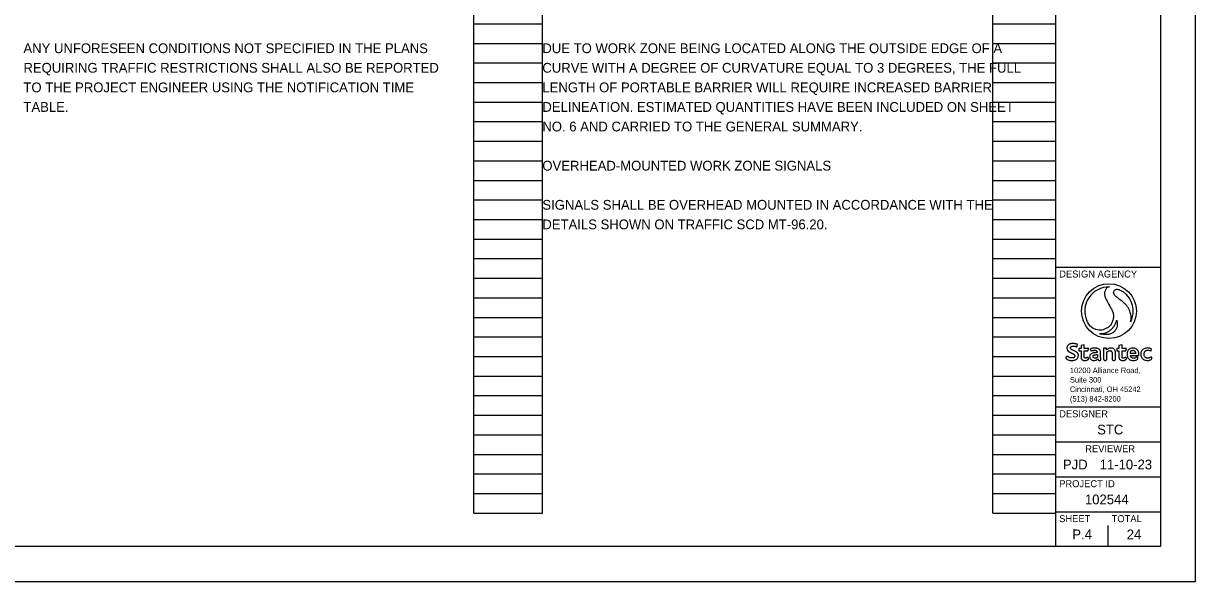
# Model space of a CAD drawing. Extents: x 0 to 34, y 0 to 22.
# Drawn here: x 17.24 to 34, y 0 to 7.98 of the extents above; entities that cross this region are included whole.
import ezdxf

# ---------------------------------------------------------------- set-up
doc = ezdxf.new("R2010")
doc.units = 0
for name, color, linetype in [('SH_Border', 7, 'Continuous'), ('SH_Cut_Line', 7, 'Continuous'), ('SH_Data', 7, 'Continuous'), ('SH_Text', 7, 'Continuous')]:
    doc.layers.add(name, color=color, linetype=linetype)

msp = doc.modelspace()

# ---------------------------------------------------------------- linework, layer by layer
at = {"layer": 'SH_Border'}
for p, q in [((32, 0.5), (32, 21.5)), ((32, 4.5), (33.5, 4.5)), ((32, 2.5), (33.5, 2.5)), ((32, 2), (33.5, 2)), ((32, 1.5), (33.5, 1.5)), ((32, 1), (33.5, 1))]:
    msp.add_line(p, q, dxfattribs=at)
msp.add_lwpolyline([(1.5, 21.5), (33.5, 21.5), (33.5, 0.5), (1.5, 0.5)], close=True, dxfattribs=at)
at = {"layer": 'SH_Cut_Line'}
msp.add_lwpolyline([(0, 0), (34, 0), (34, 22), (0, 22)], close=True, dxfattribs=at)
at = {"layer": 'SH_Data'}
for p, q in [((23.68, 0.98), (23.68, 21.14)), ((24.66, 0.98), (24.66, 21.14)), ((31.1, 0.98), (31.1, 21.14)), ((32, 0.98), (32, 21.14)), ((23.68, 7.98), (24.66, 7.98)), ((31.1, 7.98), (32, 7.98)), ((23.68, 7.7), (24.66, 7.7)), ((31.1, 7.7), (32, 7.7)), ((23.68, 7.42), (24.66, 7.42)), ((31.1, 7.42), (32, 7.42)), ((23.68, 7.14), (24.66, 7.14)), ((31.1, 7.14), (32, 7.14)), ((23.68, 6.86), (24.66, 6.86)), ((31.1, 6.86), (32, 6.86)), ((23.68, 6.58), (24.66, 6.58)), ((31.1, 6.58), (32, 6.58)), ((23.68, 6.3), (24.66, 6.3)), ((31.1, 6.3), (32, 6.3)), ((23.68, 6.02), (24.66, 6.02)), ((31.1, 6.02), (32, 6.02)), ((23.68, 5.74), (24.66, 5.74)), ((31.1, 5.74), (32, 5.74)), ((23.68, 5.46), (24.66, 5.46)), ((31.1, 5.46), (32, 5.46)), ((23.68, 5.18), (24.66, 5.18)), ((31.1, 5.18), (32, 5.18)), ((23.68, 4.9), (24.66, 4.9)), ((31.1, 4.9), (32, 4.9)), ((23.68, 4.62), (24.66, 4.62)), ((31.1, 4.62), (32, 4.62)), ((23.68, 4.34), (24.66, 4.34)), ((31.1, 4.34), (32, 4.34)), ((23.68, 4.06), (24.66, 4.06)), ((31.1, 4.06), (32, 4.06)), ((23.68, 3.78), (24.66, 3.78)), ((31.1, 3.78), (32, 3.78)), ((23.68, 3.5), (24.66, 3.5)), ((31.1, 3.5), (32, 3.5)), ((32.75, 3.5), (32.75, 3.5)), ((23.68, 3.22), (24.66, 3.22)), ((31.1, 3.22), (32, 3.22)), ((23.68, 2.94), (24.66, 2.94)), ((31.1, 2.94), (32, 2.94)), ((23.68, 2.66), (24.66, 2.66)), ((31.1, 2.66), (32, 2.66)), ((23.68, 2.38), (24.66, 2.38)), ((31.1, 2.38), (32, 2.38)), ((23.68, 2.1), (24.66, 2.1)), ((31.1, 2.1), (32, 2.1)), ((23.68, 1.82), (24.66, 1.82)), ((31.1, 1.82), (32, 1.82)), ((23.68, 1.54), (24.66, 1.54)), ((31.1, 1.54), (32, 1.54)), ((23.68, 1.26), (24.66, 1.26)), ((31.1, 1.26), (32, 1.26)), ((23.68, 0.98), (24.66, 0.98)), ((31.1, 0.98), (32, 0.98)), ((32.375, 0.675), (32.375, 0.675)), ((32.75, 0.5), (32.75, 0.8))]:
    msp.add_line(p, q, dxfattribs=at)
at = {"layer": 'SH_Text'}
for p, q in [((32.302, 3.358), (32.314, 3.392)), ((32.409, 3.389), (32.362, 3.376)), ((32.362, 3.376), (32.362, 3.336)), ((32.409, 3.336), (32.409, 3.389)), ((32.951, 3.389), (32.903, 3.376)), ((32.903, 3.376), (32.903, 3.336)), ((32.951, 3.336), (32.951, 3.389)), ((32.362, 3.336), (32.331, 3.336)), ((32.331, 3.336), (32.331, 3.303)), ((32.331, 3.303), (32.362, 3.303)), ((32.472, 3.336), (32.409, 3.336)), ((32.409, 3.219), (32.409, 3.303)), ((32.409, 3.303), (32.46, 3.303)), ((32.46, 3.303), (32.472, 3.336)), ((32.492, 3.325), (32.506, 3.297)), ((32.596, 3.247), (32.596, 3.209)), ((32.725, 3.337), (32.684, 3.337)), ((32.684, 3.337), (32.684, 3.184)), ((32.728, 3.317), (32.725, 3.337)), ((32.731, 3.184), (32.731, 3.285)), ((32.903, 3.336), (32.873, 3.336)), ((32.873, 3.336), (32.873, 3.303)), ((32.873, 3.303), (32.904, 3.303)), ((32.95, 3.219), (32.951, 3.303)), ((33.013, 3.336), (32.951, 3.336)), ((32.951, 3.303), (33.002, 3.303)), ((33.002, 3.303), (33.013, 3.336)), ((33.141, 3.265), (33.068, 3.265)), ((33.068, 3.236), (33.19, 3.236)), ((33.359, 3.296), (33.37, 3.327))]:
    msp.add_line(p, q, dxfattribs=at)
for points in [[(32.769, 4.215), (32.769, 4.215)], [(32.968, 4.147), (32.968, 4.147)]]:
    msp.add_lwpolyline(points, dxfattribs=at)
msp.add_circle((32.762, 3.869), 0.392, dxfattribs=at)
for start, end in [(88.7666, 203.6845), (88.7601, 88.7666), (333.7815, 53.4326), (247.1184, 251.458)]:
    msp.add_arc((32.762, 3.869), 0.346, start, end, dxfattribs=at)
for points, degree in [([(32.769, 4.215), (32.761, 4.213), (32.741, 4.209), (32.715, 4.183), (32.696, 4.14), (32.699, 4.091), (32.716, 4.045), (32.742, 3.999), (32.768, 3.949), (32.798, 3.902), (32.819, 3.854), (32.828, 3.802), (32.822, 3.749), (32.807, 3.702), (32.777, 3.658), (32.739, 3.627), (32.698, 3.609), (32.661, 3.597), (32.62, 3.597), (32.575, 3.604), (32.53, 3.624), (32.482, 3.665), (32.459, 3.705), (32.445, 3.73)], 3), ([(32.769, 4.215), (32.769, 4.215), (32.769, 4.215), (32.769, 4.215)], 2), ([(33.072, 3.716), (33.075, 3.728), (33.08, 3.751), (33.079, 3.788), (33.076, 3.82), (33.066, 3.85), (33.055, 3.884), (33.036, 3.922), (33.008, 3.957), (32.971, 3.994), (32.926, 4.027), (32.879, 4.065), (32.841, 4.093), (32.828, 4.127), (32.828, 4.152), (32.841, 4.169), (32.857, 4.181), (32.879, 4.183), (32.905, 4.178), (32.936, 4.165), (32.957, 4.153), (32.968, 4.147)], 3), ([(32.627, 3.55), (32.636, 3.549), (32.656, 3.548), (32.69, 3.554), (32.728, 3.563), (32.763, 3.583), (32.795, 3.606), (32.824, 3.637), (32.849, 3.673), (32.865, 3.71), (32.869, 3.732), (32.872, 3.742)], 3), ([(32.872, 3.742), (32.874, 3.734), (32.881, 3.711), (32.882, 3.674), (32.876, 3.633), (32.855, 3.596), (32.827, 3.562), (32.786, 3.543), (32.742, 3.533), (32.697, 3.532), (32.666, 3.538), (32.652, 3.541)], 3), ([(32.314, 3.392), (32.312, 3.393), (32.302, 3.398), (32.284, 3.402), (32.262, 3.405), (32.242, 3.406), (32.225, 3.404), (32.209, 3.401), (32.193, 3.395), (32.179, 3.385), (32.168, 3.371), (32.162, 3.357), (32.16, 3.344), (32.161, 3.332), (32.163, 3.321), (32.168, 3.311), (32.174, 3.303), (32.181, 3.295), (32.19, 3.288), (32.201, 3.282), (32.214, 3.275), (32.229, 3.268), (32.244, 3.262), (32.256, 3.255), (32.266, 3.248), (32.272, 3.24), (32.274, 3.231), (32.274, 3.223), (32.27, 3.214), (32.263, 3.206), (32.25, 3.2), (32.236, 3.198), (32.219, 3.199), (32.205, 3.202), (32.194, 3.208), (32.184, 3.212), (32.178, 3.218), (32.172, 3.22), (32.166, 3.222), (32.161, 3.222), (32.155, 3.22), (32.15, 3.216), (32.146, 3.209), (32.146, 3.203), (32.147, 3.196), (32.152, 3.189), (32.162, 3.179), (32.181, 3.17), (32.203, 3.164), (32.226, 3.163), (32.245, 3.163), (32.262, 3.165), (32.277, 3.17), (32.293, 3.177), (32.308, 3.189), (32.319, 3.203), (32.324, 3.22), (32.325, 3.236), (32.323, 3.25), (32.317, 3.261), (32.311, 3.273), (32.299, 3.282), (32.286, 3.291), (32.271, 3.298), (32.255, 3.305), (32.239, 3.312), (32.225, 3.32), (32.216, 3.328), (32.212, 3.337), (32.211, 3.345), (32.213, 3.353), (32.219, 3.36), (32.226, 3.365), (32.236, 3.369), (32.248, 3.369), (32.26, 3.369), (32.271, 3.367), (32.282, 3.365), (32.293, 3.362), (32.299, 3.359), (32.302, 3.358)], 3), ([(32.362, 3.303), (32.362, 3.273), (32.362, 3.242), (32.362, 3.207), (32.364, 3.198), (32.367, 3.187), (32.373, 3.179), (32.38, 3.173), (32.387, 3.168), (32.398, 3.164), (32.413, 3.163), (32.429, 3.163), (32.445, 3.165), (32.457, 3.172), (32.466, 3.179), (32.47, 3.187), (32.471, 3.194), (32.469, 3.2), (32.466, 3.204), (32.462, 3.206), (32.458, 3.207), (32.453, 3.207), (32.448, 3.206), (32.444, 3.202), (32.439, 3.199), (32.433, 3.196), (32.427, 3.194), (32.42, 3.195), (32.415, 3.198), (32.41, 3.202), (32.408, 3.21), (32.408, 3.215), (32.409, 3.219)], 3), ([(32.596, 3.275), (32.593, 3.275), (32.583, 3.275), (32.566, 3.274), (32.545, 3.273), (32.526, 3.269), (32.508, 3.261), (32.492, 3.248), (32.485, 3.229), (32.486, 3.211), (32.489, 3.196), (32.498, 3.183), (32.512, 3.171), (32.531, 3.164), (32.551, 3.163), (32.57, 3.166), (32.584, 3.171), (32.594, 3.178), (32.598, 3.183), (32.601, 3.185)], 3), ([(32.601, 3.185), (32.601, 3.184), (32.601, 3.18), (32.605, 3.174), (32.611, 3.167), (32.621, 3.163), (32.632, 3.163), (32.642, 3.165), (32.646, 3.173), (32.646, 3.181), (32.644, 3.192), (32.641, 3.221), (32.643, 3.252), (32.643, 3.285), (32.639, 3.302), (32.63, 3.316), (32.62, 3.327), (32.604, 3.336), (32.584, 3.341), (32.56, 3.342), (32.536, 3.34), (32.513, 3.335), (32.498, 3.328), (32.492, 3.325)], 3), ([(32.506, 3.297), (32.508, 3.298), (32.515, 3.302), (32.526, 3.305), (32.539, 3.308), (32.551, 3.309), (32.564, 3.309), (32.576, 3.305), (32.586, 3.299), (32.593, 3.291), (32.596, 3.282), (32.596, 3.277), (32.596, 3.275)], 3), ([(32.596, 3.209), (32.595, 3.208), (32.591, 3.205), (32.583, 3.2), (32.571, 3.196), (32.559, 3.195), (32.549, 3.198), (32.541, 3.202), (32.537, 3.208), (32.533, 3.215), (32.533, 3.222), (32.534, 3.229), (32.539, 3.236), (32.546, 3.24), (32.555, 3.244), (32.566, 3.246), (32.578, 3.246), (32.589, 3.247), (32.594, 3.247), (32.596, 3.247)], 3), ([(32.731, 3.285), (32.732, 3.286), (32.736, 3.289), (32.743, 3.293), (32.754, 3.3), (32.766, 3.304), (32.78, 3.304), (32.792, 3.3), (32.801, 3.291), (32.806, 3.28), (32.808, 3.265), (32.807, 3.244), (32.808, 3.216), (32.806, 3.193), (32.807, 3.177), (32.813, 3.169), (32.822, 3.163), (32.833, 3.163), (32.844, 3.165), (32.853, 3.172), (32.855, 3.184), (32.853, 3.207), (32.854, 3.234), (32.854, 3.264), (32.855, 3.283), (32.852, 3.3), (32.847, 3.311), (32.839, 3.323), (32.825, 3.333), (32.809, 3.341), (32.79, 3.341), (32.772, 3.34), (32.757, 3.335), (32.743, 3.329), (32.734, 3.321), (32.729, 3.318), (32.728, 3.317)], 3), ([(32.904, 3.303), (32.904, 3.273), (32.903, 3.242), (32.904, 3.207), (32.905, 3.198), (32.909, 3.187), (32.915, 3.179), (32.922, 3.173), (32.929, 3.168), (32.94, 3.164), (32.955, 3.163), (32.971, 3.163), (32.987, 3.165), (32.999, 3.172), (33.008, 3.179), (33.012, 3.187), (33.012, 3.194), (33.011, 3.2), (33.008, 3.204), (33.004, 3.206), (33, 3.207), (32.995, 3.207), (32.99, 3.206), (32.986, 3.202), (32.981, 3.199), (32.975, 3.196), (32.969, 3.194), (32.962, 3.195), (32.957, 3.198), (32.952, 3.202), (32.95, 3.21), (32.95, 3.215), (32.95, 3.219)], 3), ([(33.19, 3.236), (33.19, 3.24), (33.19, 3.252), (33.188, 3.271), (33.183, 3.292), (33.173, 3.308), (33.162, 3.322), (33.147, 3.332), (33.129, 3.339), (33.108, 3.341), (33.088, 3.34), (33.069, 3.334), (33.052, 3.325), (33.038, 3.311), (33.028, 3.295), (33.023, 3.277), (33.021, 3.258), (33.021, 3.238), (33.025, 3.22), (33.032, 3.202), (33.043, 3.186), (33.06, 3.174), (33.081, 3.164), (33.106, 3.163), (33.128, 3.163), (33.147, 3.167), (33.162, 3.174), (33.173, 3.184), (33.177, 3.194), (33.175, 3.202), (33.171, 3.209), (33.164, 3.211), (33.158, 3.211), (33.151, 3.209), (33.142, 3.204), (33.132, 3.197), (33.119, 3.195), (33.108, 3.194), (33.096, 3.197), (33.087, 3.204), (33.078, 3.211), (33.072, 3.221), (33.069, 3.23), (33.068, 3.234), (33.068, 3.236)], 3), ([(33.068, 3.265), (33.068, 3.267), (33.068, 3.27), (33.068, 3.278), (33.071, 3.287), (33.076, 3.296), (33.085, 3.304), (33.097, 3.309), (33.11, 3.309), (33.123, 3.305), (33.133, 3.299), (33.138, 3.287), (33.14, 3.276), (33.141, 3.269), (33.141, 3.265)], 3), ([(33.37, 3.327), (33.366, 3.33), (33.356, 3.335), (33.337, 3.34), (33.312, 3.343), (33.287, 3.34), (33.262, 3.332), (33.242, 3.318), (33.227, 3.3), (33.218, 3.278), (33.215, 3.255), (33.216, 3.23), (33.225, 3.209), (33.237, 3.192), (33.254, 3.178), (33.277, 3.167), (33.304, 3.163), (33.329, 3.164), (33.35, 3.17), (33.366, 3.177), (33.377, 3.187), (33.377, 3.197), (33.377, 3.205), (33.372, 3.209), (33.367, 3.212), (33.361, 3.212), (33.354, 3.211), (33.347, 3.205), (33.337, 3.201), (33.327, 3.197), (33.314, 3.196), (33.299, 3.197), (33.285, 3.204), (33.275, 3.215), (33.266, 3.228), (33.264, 3.243), (33.262, 3.257), (33.266, 3.272), (33.271, 3.285), (33.28, 3.296), (33.291, 3.304), (33.304, 3.309), (33.319, 3.31), (33.334, 3.309), (33.348, 3.304), (33.356, 3.299), (33.359, 3.296)], 3), ([(32.684, 3.184), (32.685, 3.182), (32.686, 3.177), (32.689, 3.17), (32.698, 3.163), (32.71, 3.163), (32.722, 3.164), (32.729, 3.172), (32.731, 3.179), (32.731, 3.182), (32.731, 3.184)], 3)]:
    msp.add_open_spline(points, degree=degree, dxfattribs=at)

# ---------------------------------------------------------------- texts
at = {"layer": 'SH_Data'}
for s, height, p in [('DESIGN AGENCY', 0.1, (32.05, 4.35)), ('DESIGNER', 0.1, (32.05, 2.35)), ('STC', 0.14, (32.593, 2.105)), ('REVIEWER', 0.1, (32.422, 1.85)), ('PJD', 0.14, (32.103, 1.605)), ('11-10-23', 0.14, (32.629, 1.605)), ('PROJECT ID', 0.1, (32.05, 1.35)), ('102544', 0.14, (32.418, 1.105)), ('SHEET', 0.1, (32.05, 0.85)), ('TOTAL', 0.1, (32.8, 0.85)), ('P.4', 0.14, (32.237, 0.605)), ('24', 0.14, (33.016, 0.605))]:
    msp.add_text(s, height=height, dxfattribs=at).set_placement(p)
at = {"layer": 'SH_Text'}
for s, p in [('ANY UNFORESEEN CONDITIONS NOT SPECIFIED IN THE PLANS', (17.24, 7.56)), ('DUE TO WORK ZONE BEING LOCATED ALONG THE OUTSIDE EDGE OF A', (24.66, 7.56)), ('REQUIRING TRAFFIC RESTRICTIONS SHALL ALSO BE REPORTED', (17.24, 7.28)), ('CURVE WITH A DEGREE OF CURVATURE EQUAL TO 3 DEGREES, THE FULL', (24.66, 7.28)), ('TO THE PROJECT ENGINEER USING THE NOTIFICATION TIME', (17.24, 7)), ('LENGTH OF PORTABLE BARRIER WILL REQUIRE INCREASED BARRIER', (24.66, 7)), ('TABLE.', (17.24, 6.72)), ('DELINEATION. ESTIMATED QUANTITIES HAVE BEEN INCLUDED ON SHEET', (24.66, 6.72)), ('NO. 6 AND CARRIED TO THE GENERAL SUMMARY. ', (24.66, 6.44)), ('OVERHEAD-MOUNTED WORK ZONE SIGNALS', (24.66, 5.88)), ('SIGNALS SHALL BE OVERHEAD MOUNTED IN ACCORDANCE WITH THE', (24.66, 5.32)), ('DETAILS SHOWN ON TRAFFIC SCD MT-96.20.', (24.66, 5.04))]:
    msp.add_text(s, height=0.14, dxfattribs=at).set_placement(p)
for s, height, p in [('10200 Alliance Road,', 0.07948, (32.204, 2.982)), ('Suite 300', 0.0795, (32.204, 2.847)), ('Cincinnati, OH 45242', 0.07948, (32.204, 2.711)), ('(513) 842-8200', 0.07948, (32.204, 2.575))]:
    msp.add_text(s, height=height, rotation=360, dxfattribs=at).set_placement(p)

doc.saveas('drawing.dxf')
